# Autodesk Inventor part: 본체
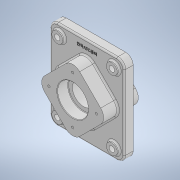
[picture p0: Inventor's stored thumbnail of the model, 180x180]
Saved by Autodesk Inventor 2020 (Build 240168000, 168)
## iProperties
Created: 2021-07
Part Number: 본체
Material: 일반
Document SubType Name: Modeling
Designer: Owner
Density: 1 g/cm^3
Appearance: 기본값
Mass: 807.977 g
Surface Area: 961.758 cm^2
Volume: 807.977 cm^3
Author: Owner
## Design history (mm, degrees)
sketch "스케치1"
  geometry: L1 (75, -90)-(-75, -90); L2 (-75, -90)-(-75, 90); L3 (-75, 90)-(75, 90); L4 (75, 90)-(75, -90); L5 (75, -90)-(-75, 90); L6 (-75, -90)-(75, 90); 1 further point
  constraints: 12 end point, 2 midpoint, 2 parallel, 1 horizontal, 1 perpendicular
  dimensions: "d0" = 150 distance of L2.end L3.end; "d1" = 180 distance of L1.end L2.end
extrude "돌출1" new body sketch "스케치1" stored distance "d2" = 18; taper "d3" = 0 deg
fillet "모깎기1" dims "d4" = 15
sketch "스케치2"
  geometry: L1 (0, -70.711)-(-70.711, 0); L2 (-70.711, 0)-(0, 70.711); L3 (0, 70.711)-(70.711, 0); L4 (70.711, 0)-(0, -70.711); L5 (0, -70.711)-(0, 70.711); L6 (-70.711, 0)-(70.711, 0); 4 further points
  constraints: 12 end point, 4 midpoint, 2 parallel, 1 coincident, 1 horizontal alignment, 1 perpendicular, 1 vertical alignment
  dimensions: "d70" = 100 distance of L1.start L1.end
extrude "돌출2" join sketch "스케치2" distance "d7" = 29; taper "d8" = 0 deg
sketch "스케치3"
  geometry: L1 (-14.142, -56.569)-(-56.569, -14.142); L2 (-56.569, 14.142)-(-14.142, 56.569); L3 (14.142, 56.569)-(56.569, 14.142); L4 (56.569, -14.142)-(14.142, -56.569); L5 (0, -70.711)-(0, 70.711); L6 (-70.711, 0)-(70.711, 0); A1 r 20 centre (-42.426, 0) between (-56.569, 14.142) and (-56.569, -14.142); A2 r 20 centre (0, -42.426) between (-14.142, -56.569) and (14.142, -56.569); A3 r 20 centre (42.426, 0) between (56.569, -14.142) and (56.569, 14.142); A4 r 20 centre (0, 42.426) between (14.142, 56.569) and (-14.142, 56.569); 3 further points
  constraints: 12 end point, 8 point on circle, 8 point on line, 8 tangent, 4 centre point, 4 midpoint, 3 equal radius, 2 parallel, 1 horizontal alignment, 1 perpendicular, 1 vertical alignment
  dimensions: "d9" = 100 distance of L5.start L6.start; "d12" = 20 radius of A1 (derived)
extrude "돌출3" join sketch "스케치3" distance "d10" = 23; taper "d11" = 0 deg
sketch "스케치4"
  geometry: C1 r 11 at (-55, 70); C2 r 11 at (55, 70); C3 r 11 at (55, -70); C4 r 11 at (-55, -70); 1 further point
  constraints: 4 centre point, 2 horizontal alignment, 2 vertical alignment
  dimensions: "d13" = 22 diameter of C1; "d14" = 22 diameter of C2; "d15" = 22 diameter of C3; "d16" = 22 diameter of C4; "d17" = 110 distance of C1.centre C2.centre; "d18" = 55 horizontal distance of point (0, 0) C1.centre (= 0.5 x d17); "d19" = 140 distance of C3.centre C2.centre; "d20" = 70 vertical distance of point (0, 0) C2.centre (= 0.5 x d19)
extrude "돌출4" join sketch "스케치4" distance "d21" = 5; taper "d22" = 0 deg
sketch "스케치5"
  geometry: C1 r 11 at (0, 0) reference; C2 r 11 at (110, 0) reference; C3 r 11 at (110, -140) reference; C4 r 11 at (0, -140) reference; 5 further points
  constraints: 4 coincident
hole "구멍1" sketch "스케치5" at (0, 0), (110, 0), (110, -140), (0, -140) diameter "d23" = 11; stored, may be unused: countersink angle "d27" = 90 deg, drill point angle "d29" = 118 deg; dims "d24" = 6, "d25" = 4, "d26" = 2, "d28" = 8
sketch "스케치6"
  geometry: 2 further points
  constraints: 1 vertical alignment
  dimensions: "d30" = 48 distance of point (0, 0) point (0, 48)
hole "구멍2" sketch "스케치6" at (0, 48) diameter "d31" = 4.917; stored, may be unused: countersink angle "d35" = 90 deg, drill point angle "d37" = 118 deg; dims "d32" = 10, "d33" = 4, "d34" = 2, "d36" = 13
sketch "스케치7"
  geometry: 2 further points
  constraints: 1 coincident
hole "구멍3" sketch "스케치7" at (0, 0) diameter "d41" = 45; stored, may be unused: countersink angle "d45" = 90 deg, drill point angle "d47" = 118 deg; dims "d42" = 10, "d43" = 62, "d44" = 22, "d46" = 13
chamfer "모따기1" distance "d48" = 1; stored, may be unused: second distance "d49" = 2, angle "d50" = 45 deg
fillet "모깎기2" dims "d51" = 1
sketch "스케치8"
  geometry: 2 further points
  constraints: 1 vertical alignment
  dimensions: "d52" = 48 distance of point (0, 0) point (0, 48)
hole "구멍4" sketch "스케치8" at (0, 48) diameter "d53" = 4.917; stored, may be unused: countersink angle "d57" = 90 deg, drill point angle "d59" = 118 deg; dims "d54" = 10, "d55" = 62, "d56" = 22, "d58" = 13
fillet "모깎기3" dims "d63" = 3
sketch "스케치9"
  geometry: L1 (60, 90)-(-60, 90) reference; 2 further points
  constraints: 1 vertical alignment, 1 other
  dimensions: "d64" = 15 distance from line of point (0, 75) L1
feature "엠보싱1" sketch "스케치9" dims "d0" = 150, "d1" = 180, "d65" = 0.5, "d66" = 0
fillet "모깎기4" dims "d67" = 3
fillet "모깎기6" dims "d69" = 3
fillet "모깎기7" dims "d71" = 20
fillet "모깎기8" dims "d72" = 3
sketch "스케치10"
  geometry: C1 r 31 at (0, 0); 1 further point
  constraints: 1 centre point, 1 coincident
  dimensions: "d73" = 62 diameter of C1
extrude "돌출5" cut sketch "스케치10" distance "d74" = 22; taper "d75" = 0 deg
fillet "모깎기9" dims "d76" = 1
chamfer "모따기2" distance "d77" = 1; stored, may be unused: second distance "d78" = 2, angle "d79" = 45 deg
node "솔리드1"
pattern_circular "원형 패턴1" dims angle "d39" = 360 deg
pattern_circular "원형 패턴2" dims angle "d61" = 360 deg
feature "A9D066F2-1C7D-4E18-AEED-F7BC21143FA4" dims "d23" = 11, "d24" = 6, "d25" = 4, "d26" = 2, "d27" = 90 deg, "d28" = 8, "d29" = 118 deg
